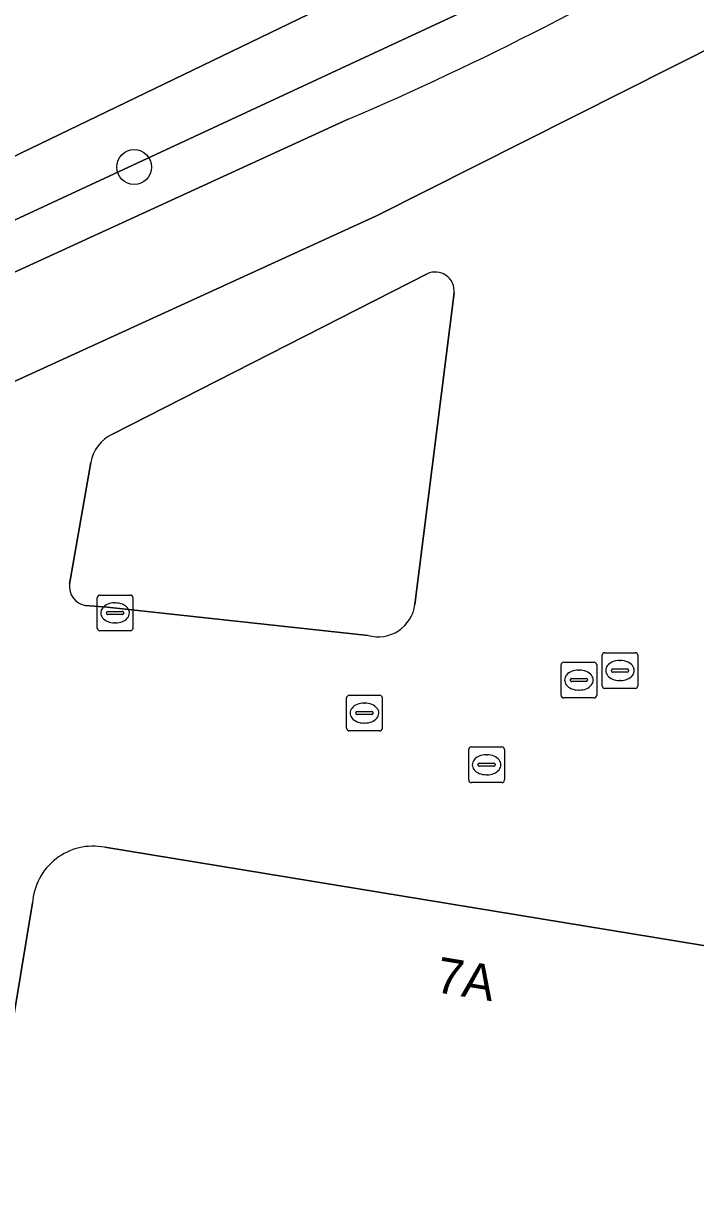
# Model space of a CAD drawing. Extents: x 161090 to 161692, y 379509 to 380907.
# Drawn here: x 161323.53 to 161342.36, y 379951.79 to 379984.68 of the extents above; entities that cross this region are included whole.
import ezdxf

# ---------------------------------------------------------------- set-up
doc = ezdxf.new("R2010")
doc.units = 0
for name, color, linetype in [('IMGEO_Boom', 7, 'Continuous'), ('IMGEO_Groenvoorziening', 7, 'Continuous'), ('IMGEO_Kolk', 7, 'Continuous'), ('IMGEO_Oever', 7, 'Continuous'), ('IMGEO_Pand', 7, 'Continuous'), ('IMGEO_Pand_nummerreeks', 7, 'Continuous'), ('IMGEO_Rijbaan_lokaal_gesloten', 7, 'Continuous'), ('IMGEO_Rioolput', 7, 'Continuous'), ('IMGEO_Voetpad_open', 7, 'Continuous'), ('IMGEO_Waterloop', 7, 'Continuous')]:
    doc.layers.add(name, color=color, linetype=linetype)

msp = doc.modelspace()

# ---------------------------------------------------------------- linework, layer by layer
at = {"layer": 'IMGEO_Boom'}
msp.add_circle((161326.632, 379980.661), 0.489, dxfattribs=at)
at = {"layer": 'IMGEO_Groenvoorziening'}
for points in [[(161345.842, 379990.137), (161336.524, 379985.328), (161319.974, 379977.646), (161316.928, 379975.983), (161310.516, 379973.076), (161303.367, 379969.522), (161253.412, 379946.694), (161253.581, 379946.317), (161253.756, 379945.988), (161281.664, 379958.627), (161332.629, 379982.003)], [(161334.839, 379977.666), (161326.021, 379973.173)], [(161334.496, 379968.4), (161335.592, 379977.135)], [(161325.416, 379972.384), (161324.819, 379968.976)], [(161325.269, 379968.378), (161325.873, 379968.331)], [(161325.873, 379968.331), (161333.185, 379967.537)]]:
    msp.add_lwpolyline(points, dxfattribs=at)
for centre, radius, start, end in [((161297.957, 380062.954), 88.064, 293.18607, 301.1178), ((161335.073, 379977.198), 0.523, 353.0575, 116.5611), ((161326.467, 379972.205), 1.066, 114.7138, 170.3247), ((161325.361, 379968.916), 0.546, 173.6526, 260.2709), ((161333.465, 379968.539), 1.041, 254.3979, 352.314)]:
    msp.add_arc(centre, radius, start, end, dxfattribs=at)
at = {"layer": 'IMGEO_Kolk'}
for p, q in [((161325.598, 379967.742), (161325.598, 379968.594)), ((161325.673, 379968.668), (161326.525, 379968.668)), ((161326.599, 379968.594), (161326.599, 379967.742)), ((161326.086, 379968.448), (161326.111, 379968.448)), ((161325.857, 379968.162), (161325.857, 379968.174)), ((161326.295, 379968.125), (161325.897, 379968.125)), ((161325.9, 379968.211), (161326.298, 379968.211)), ((161326.109, 379967.888), (161326.084, 379967.888)), ((161326.341, 379968.174), (161326.341, 379968.162)), ((161326.525, 379967.668), (161325.673, 379967.668)), ((161339.739, 379966.127), (161339.739, 379966.979)), ((161339.814, 379967.053), (161340.666, 379967.053)), ((161340.74, 379966.979), (161340.74, 379966.127)), ((161340.041, 379966.596), (161340.439, 379966.596)), ((161340.227, 379966.833), (161340.252, 379966.833)), ((161339.998, 379966.547), (161339.998, 379966.559)), ((161340.436, 379966.51), (161340.038, 379966.51)), ((161340.25, 379966.273), (161340.225, 379966.273)), ((161340.482, 379966.559), (161340.482, 379966.547)), ((161340.666, 379966.053), (161339.814, 379966.053))]:
    msp.add_line(p, q, dxfattribs=at)
for points in [[(161325.598, 379967.742), (161325.598, 379968.594)], [(161325.673, 379968.668), (161326.525, 379968.668)], [(161326.599, 379968.594), (161326.599, 379967.742)], [(161326.525, 379967.668), (161325.673, 379967.668)], [(161339.739, 379966.127), (161339.739, 379966.979)], [(161339.814, 379967.053), (161340.666, 379967.053)], [(161340.74, 379966.979), (161340.74, 379966.127)], [(161340.666, 379966.053), (161339.814, 379966.053)]]:
    msp.add_lwpolyline(points, dxfattribs=at)
for centre, radius, start, end in [((161325.675, 379968.592), 0.0765, 91.552, 178.448), ((161325.675, 379968.592), 0.0765, 91.552, 178.448), ((161326.523, 379968.592), 0.0765, 1.552, 88.448), ((161326.523, 379968.592), 0.0765, 1.552, 88.448), ((161325.897, 379968.171), 0.0403, 85.8775, 175.7526), ((161325.894, 379968.161), 0.0366, 178.938, 274.7102), ((161326.298, 379968.168), 0.043, 264.8664, 352.4533), ((161326.302, 379968.173), 0.0386, 1.7309, 96.639), ((161325.675, 379967.744), 0.0765, 181.552, 268.448), ((161325.675, 379967.744), 0.0765, 181.552, 268.448), ((161326.523, 379967.744), 0.0765, 271.552, 358.448), ((161326.523, 379967.744), 0.0765, 271.552, 358.448), ((161339.816, 379966.977), 0.0765, 91.552, 178.448), ((161339.816, 379966.977), 0.0765, 91.552, 178.448), ((161340.664, 379966.977), 0.0765, 1.552, 88.448), ((161340.664, 379966.977), 0.0765, 1.552, 88.448), ((161340.038, 379966.556), 0.0403, 85.8775, 175.7526), ((161340.443, 379966.558), 0.0386, 1.7309, 96.639), ((161340.035, 379966.546), 0.0366, 178.938, 274.7102), ((161340.439, 379966.553), 0.043, 264.8664, 352.4533), ((161339.816, 379966.129), 0.0765, 181.552, 268.448), ((161339.816, 379966.129), 0.0765, 181.552, 268.448), ((161340.664, 379966.129), 0.0765, 271.552, 358.448), ((161340.664, 379966.129), 0.0765, 271.552, 358.448)]:
    msp.add_arc(centre, radius, start, end, dxfattribs=at)
for centre, major_axis, ratio, start_param, end_param in [((161326.085, 379968.168), (-0.387, 0.002), 0.722429, 4.712389, 7.853982), ((161326.11, 379968.168), (-0.39, 0.002), 0.717154, 1.570796, 4.712389), ((161340.226, 379966.553), (-0.387, 0.002), 0.722429, 4.712389, 7.853982), ((161340.251, 379966.553), (-0.39, 0.002), 0.717154, 1.570796, 4.712389)]:
    msp.add_ellipse(centre, major_axis=major_axis, ratio=ratio, start_param=start_param, end_param=end_param, dxfattribs=at)
at = {"layer": 'IMGEO_Oever'}
for points in [[(161348.33, 379993.974), (161344.015, 379991.183), (161341.448, 379989.744), (161313.23, 379976.116), (161295.894, 379968.025), (161252.681, 379948.316), (161253.412, 379946.694), (161303.367, 379969.522)], [(161303.367, 379969.522), (161310.516, 379973.076), (161316.928, 379975.983), (161319.974, 379977.646), (161336.524, 379985.328), (161345.842, 379990.137)]]:
    msp.add_lwpolyline(points, dxfattribs=at)
at = {"layer": 'IMGEO_Pand'}
for points in [[(161368.38, 379956.294), (161364.656, 379955.185), (161351.399, 379957.383), (161349.186, 379956.677), (161345.942, 379955.648), (161345.078, 379958.432), (161325.807, 379961.6)], [(161323.784, 379960.039), (161323.28, 379956.993), (161321.468, 379946.045), (161305.762, 379941.125), (161301.265, 379939.701), (161305.545, 379925.891), (161371.456, 379946.414), (161368.38, 379956.294)]]:
    msp.add_lwpolyline(points, dxfattribs=at)
msp.add_arc((161325.482, 379959.93), 1.701, 78.9834, 176.326, dxfattribs=at)
at = {"layer": 'IMGEO_Rijbaan_lokaal_gesloten'}
for points in [[(161281.789, 379955.678), (161290.836, 379959.816), (161294.519, 379961.501), (161311.588, 379969.309), (161333.424, 379979.297), (161343.123, 379984.181)], [(161332.629, 379982.003), (161281.664, 379958.627), (161253.756, 379945.988), (161253.97, 379945.584), (161252.234, 379944.82), (161252.058, 379945.219), (161238.961, 379939.287), (161230.89, 379935.832)]]:
    msp.add_lwpolyline(points, dxfattribs=at)
msp.add_arc((161297.957, 380062.954), 88.064, 293.18607, 301.1178, dxfattribs=at)
at = {"layer": 'IMGEO_Rioolput'}
for p, q in [((161338.588, 379965.859), (161338.588, 379966.711)), ((161338.663, 379966.785), (161339.515, 379966.785)), ((161339.589, 379966.711), (161339.589, 379965.859)), ((161338.847, 379966.279), (161338.847, 379966.291)), ((161339.285, 379966.242), (161338.887, 379966.242)), ((161338.89, 379966.328), (161339.288, 379966.328)), ((161339.076, 379966.565), (161339.101, 379966.565)), ((161339.331, 379966.291), (161339.331, 379966.279)), ((161339.099, 379966.005), (161339.074, 379966.005)), ((161332.582, 379964.935), (161332.582, 379965.787)), ((161332.657, 379965.861), (161333.509, 379965.861)), ((161333.07, 379965.641), (161333.095, 379965.641)), ((161333.583, 379965.787), (161333.583, 379964.935)), ((161339.515, 379965.785), (161338.663, 379965.785)), ((161332.841, 379965.355), (161332.841, 379965.367)), ((161333.279, 379965.318), (161332.881, 379965.318)), ((161332.884, 379965.404), (161333.282, 379965.404)), ((161333.325, 379965.367), (161333.325, 379965.355)), ((161333.093, 379965.081), (161333.068, 379965.081)), ((161333.509, 379964.861), (161332.657, 379964.861)), ((161336.003, 379963.486), (161336.003, 379964.338)), ((161336.078, 379964.412), (161336.93, 379964.412)), ((161337.004, 379964.338), (161337.004, 379963.486)), ((161336.305, 379963.955), (161336.703, 379963.955)), ((161336.491, 379964.192), (161336.516, 379964.192)), ((161336.262, 379963.906), (161336.262, 379963.918)), ((161336.7, 379963.869), (161336.302, 379963.869)), ((161336.514, 379963.632), (161336.489, 379963.632)), ((161336.746, 379963.918), (161336.746, 379963.906)), ((161336.93, 379963.412), (161336.078, 379963.412))]:
    msp.add_line(p, q, dxfattribs=at)
for points in [[(161338.588, 379965.859), (161338.588, 379966.711)], [(161338.663, 379966.785), (161339.515, 379966.785)], [(161339.589, 379966.711), (161339.589, 379965.859)], [(161332.582, 379964.935), (161332.582, 379965.787)], [(161332.657, 379965.861), (161333.509, 379965.861)], [(161333.583, 379965.787), (161333.583, 379964.935)], [(161339.515, 379965.785), (161338.663, 379965.785)], [(161333.509, 379964.861), (161332.657, 379964.861)], [(161336.003, 379963.486), (161336.003, 379964.338)], [(161336.078, 379964.412), (161336.93, 379964.412)], [(161337.004, 379964.338), (161337.004, 379963.486)], [(161336.93, 379963.412), (161336.078, 379963.412)]]:
    msp.add_lwpolyline(points, dxfattribs=at)
for centre, radius, start, end in [((161338.665, 379966.709), 0.0765, 91.552, 178.448), ((161338.665, 379966.709), 0.0765, 91.552, 178.448), ((161339.513, 379966.709), 0.0765, 1.552, 88.448), ((161339.513, 379966.709), 0.0765, 1.552, 88.448), ((161338.887, 379966.288), 0.0403, 85.8775, 175.7526), ((161338.884, 379966.278), 0.0366, 178.938, 274.7102), ((161339.288, 379966.285), 0.043, 264.8664, 352.4533), ((161339.292, 379966.29), 0.0386, 1.7309, 96.639), ((161332.659, 379965.785), 0.0765, 91.552, 178.448), ((161332.659, 379965.785), 0.0765, 91.552, 178.448), ((161333.507, 379965.785), 0.0765, 1.552, 88.448), ((161333.507, 379965.785), 0.0765, 1.552, 88.448), ((161338.665, 379965.861), 0.0765, 181.552, 268.448), ((161338.665, 379965.861), 0.0765, 181.552, 268.448), ((161339.513, 379965.861), 0.0765, 271.552, 358.448), ((161339.513, 379965.861), 0.0765, 271.552, 358.448), ((161332.881, 379965.364), 0.0403, 85.8775, 175.7526), ((161332.878, 379965.354), 0.0366, 178.938, 274.7102), ((161333.282, 379965.361), 0.043, 264.8664, 352.4533), ((161333.286, 379965.366), 0.0386, 1.7309, 96.639), ((161332.659, 379964.937), 0.0765, 181.552, 268.448), ((161332.659, 379964.937), 0.0765, 181.552, 268.448), ((161333.507, 379964.937), 0.0765, 271.552, 358.448), ((161333.507, 379964.937), 0.0765, 271.552, 358.448), ((161336.08, 379964.336), 0.0765, 91.552, 178.448), ((161336.08, 379964.336), 0.0765, 91.552, 178.448), ((161336.928, 379964.336), 0.0765, 1.552, 88.448), ((161336.928, 379964.336), 0.0765, 1.552, 88.448), ((161336.302, 379963.915), 0.0403, 85.8775, 175.7526), ((161336.707, 379963.917), 0.0386, 1.7309, 96.639), ((161336.299, 379963.905), 0.0366, 178.938, 274.7102), ((161336.703, 379963.912), 0.043, 264.8664, 352.4533), ((161336.08, 379963.488), 0.0765, 181.552, 268.448), ((161336.08, 379963.488), 0.0765, 181.552, 268.448), ((161336.928, 379963.488), 0.0765, 271.552, 358.448), ((161336.928, 379963.488), 0.0765, 271.552, 358.448)]:
    msp.add_arc(centre, radius, start, end, dxfattribs=at)
for centre, major_axis, ratio, start_param, end_param in [((161339.075, 379966.285), (-0.387, 0.002), 0.722429, 4.712389, 7.853982), ((161339.1, 379966.285), (-0.39, 0.002), 0.717154, 1.570796, 4.712389), ((161333.069, 379965.361), (-0.387, 0.002), 0.722429, 4.712389, 7.853982), ((161333.094, 379965.361), (-0.39, 0.002), 0.717154, 1.570796, 4.712389), ((161336.49, 379963.912), (-0.387, 0.002), 0.722429, 4.712389, 7.853982), ((161336.515, 379963.912), (-0.39, 0.002), 0.717154, 1.570796, 4.712389)]:
    msp.add_ellipse(centre, major_axis=major_axis, ratio=ratio, start_param=start_param, end_param=end_param, dxfattribs=at)
at = {"layer": 'IMGEO_Voetpad_open'}
for points in [[(161343.123, 379984.181), (161333.424, 379979.297), (161311.588, 379969.309), (161311.762, 379968.753), (161314.896, 379958.692), (161297.117, 379953.134), (161294.519, 379961.501), (161290.836, 379959.816), (161292.199, 379955.424), (161296.842, 379940.459), (161300.674, 379941.609), (161298.321, 379949.198), (161302.832, 379950.607), (161323.28, 379956.993), (161323.784, 379960.039)], [(161326.021, 379973.173), (161334.839, 379977.666)], [(161335.592, 379977.135), (161334.496, 379968.4)], [(161324.819, 379968.976), (161325.416, 379972.384)], [(161325.807, 379961.6), (161345.078, 379958.432), (161345.942, 379955.648), (161349.186, 379956.677), (161351.399, 379957.383), (161358.278, 379964.544), (161362.006, 379964.159), (161363.942, 379963.944), (161397.506, 379960.313), (161397.895, 379960.265), (161397.951, 379960.619), (161398.129, 379960.598), (161398.151, 379965.247), (161358.609, 379971.404)], [(161333.185, 379967.537), (161325.873, 379968.331), (161325.269, 379968.378)]]:
    msp.add_lwpolyline(points, dxfattribs=at)
for centre, radius, start, end in [((161335.073, 379977.198), 0.523, 353.0575, 116.5611), ((161326.467, 379972.205), 1.066, 114.7138, 170.3247), ((161325.361, 379968.916), 0.546, 173.6526, 260.2709), ((161333.465, 379968.539), 1.041, 254.3979, 352.314), ((161325.482, 379959.93), 1.701, 78.9834, 176.326)]:
    msp.add_arc(centre, radius, start, end, dxfattribs=at)
at = {"layer": 'IMGEO_Waterloop'}
msp.add_lwpolyline([(161251.134, 379947.611), (161252.681, 379948.316), (161295.894, 379968.025), (161313.23, 379976.116), (161341.448, 379989.744), (161344.015, 379991.183), (161348.33, 379993.974)], dxfattribs=at)

# ---------------------------------------------------------------- texts
at = {"layer": 'IMGEO_Pand_nummerreeks'}
msp.add_text('7A', height=1, rotation=350.6648, dxfattribs=at).set_placement((161335.035, 379957.549))

doc.saveas('drawing.dxf')
